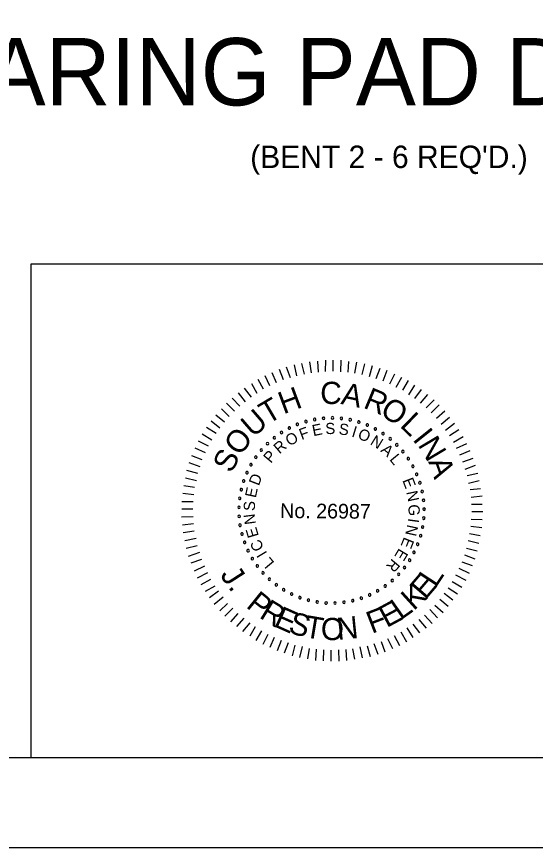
# Model space of a CAD drawing. Extents: x -125.5 to -89.4, y -5.1 to 16.9.
# Drawn here: x -102.979 to -100.09, y -5.066 to -0.44 of the extents above; entities that cross this region are included whole.
import ezdxf

# ---------------------------------------------------------------- set-up
doc = ezdxf.new("R2010")
doc.units = 0
for name, color, linetype in [('BR_BORDER LINES', 7, 'Continuous'), ('BR_TEXT', 7, 'Continuous'), ('Level 31', 7, 'Continuous')]:
    doc.layers.add(name, color=color, linetype=linetype)

msp = doc.modelspace()

# ---------------------------------------------------------------- linework, layer by layer
at = {"layer": 'BR_BORDER LINES'}
for p, q in [((-102.8989, -1.8161), (-97.5337, -1.8161)), ((-102.8989, -4.5661), (-102.8989, -1.8161)), ((-123.6994, -4.5662), (-90.0334, -4.5662))]:
    msp.add_line(p, q, dxfattribs=at)
at = {"layer": 'BR_TEXT'}
for p, q in [((-101.2977, -2.419), (-101.3015, -2.3581)), ((-101.2582, -2.4168), (-101.2576, -2.3524)), ((-101.2161, -2.4146), (-101.2156, -2.3528)), ((-101.1741, -2.4175), (-101.1718, -2.3531)), ((-101.4937, -2.4629), (-101.5147, -2.4044)), ((-101.4541, -2.4504), (-101.476, -2.3927)), ((-101.418, -2.4404), (-101.4312, -2.3793)), ((-101.3767, -2.4304), (-101.3908, -2.3711)), ((-101.3372, -2.423), (-101.3461, -2.362)), ((-101.1338, -2.4204), (-101.129, -2.3595)), ((-101.0952, -2.425), (-101.0844, -2.3642)), ((-101.0549, -2.4331), (-101.0407, -2.374)), ((-101.0138, -2.4437), (-100.9979, -2.3829)), ((-100.977, -2.4543), (-100.9551, -2.397)), ((-101.5695, -2.4966), (-101.5957, -2.4406)), ((-101.5325, -2.4798), (-101.556, -2.4238)), ((-100.9376, -2.4675), (-100.9157, -2.4093)), ((-100.9017, -2.485), (-100.8738, -2.4294)), ((-100.8658, -2.5024), (-100.8345, -2.4469)), ((-101.6394, -2.5381), (-101.6698, -2.4838)), ((-101.604, -2.5144), (-101.6344, -2.46)), ((-100.8282, -2.5208), (-100.796, -2.467)), ((-100.795, -2.5451), (-100.761, -2.4913)), ((-101.7041, -2.5847), (-101.744, -2.5346)), ((-101.6704, -2.5593), (-101.7095, -2.5083)), ((-100.7617, -2.5668), (-100.7252, -2.5165)), ((-100.7293, -2.5928), (-100.6886, -2.5434)), ((-101.7369, -2.6094), (-101.7786, -2.5644)), ((-100.6977, -2.618), (-100.6545, -2.5737)), ((-101.7958, -2.6673), (-101.8392, -2.6248)), ((-101.7663, -2.6366), (-101.8106, -2.5925)), ((-100.6697, -2.6456), (-100.6264, -2.6022)), ((-100.6416, -2.6768), (-100.594, -2.6351)), ((-101.8209, -2.6988), (-101.8704, -2.6598)), ((-100.6144, -2.7088), (-100.5677, -2.6705)), ((-101.8686, -2.761), (-101.9224, -2.728)), ((-101.8469, -2.732), (-101.8964, -2.6922)), ((-100.5906, -2.7424), (-100.5414, -2.7033)), ((-101.893, -2.7977), (-101.9467, -2.7656)), ((-100.5686, -2.7718), (-100.516, -2.7396)), ((-101.9104, -2.8319), (-101.9668, -2.804)), ((-100.5466, -2.8089), (-100.4931, -2.7776)), ((-100.5288, -2.8433), (-100.4711, -2.8164)), ((-101.9279, -2.8687), (-101.9852, -2.8433)), ((-100.5111, -2.8804), (-100.4543, -2.856)), ((-101.9454, -2.9072), (-102.0035, -2.8852)), ((-100.4943, -2.9192), (-100.4374, -2.8982)), ((-101.9577, -2.9474), (-102.0193, -2.9246)), ((-100.4809, -2.9596), (-100.4232, -2.9378)), ((-101.97, -2.9833), (-102.0308, -2.9682)), ((-100.4708, -2.9957), (-100.4107, -2.9816)), ((-101.9878, -3.0613), (-102.0487, -3.0531)), ((-101.9772, -3.0253), (-102.0397, -3.0094)), ((-100.4626, -3.0378), (-100.4024, -3.0229)), ((-101.9925, -3.1024), (-102.0542, -3.0951)), ((-100.4543, -3.074), (-100.3951, -3.0667)), ((-101.9954, -3.1419), (-102.0597, -3.1414)), ((-100.4478, -3.1152), (-100.3868, -3.1088)), ((-101.9974, -3.183), (-102.06, -3.1825)), ((-100.4464, -3.1547), (-100.3863, -3.1552)), ((-101.9961, -3.226), (-102.0604, -3.2272)), ((-100.4442, -3.1959), (-100.3833, -3.1964)), ((-101.9938, -3.2646), (-102.0556, -3.2718)), ((-100.4492, -3.2774), (-100.3883, -3.2856)), ((-100.4471, -3.2388), (-100.3871, -3.241)), ((-101.9898, -3.3058), (-102.0509, -3.3148)), ((-100.4564, -3.3185), (-100.3972, -3.3284)), ((-101.9799, -3.3454), (-102.0426, -3.3586)), ((-100.4653, -3.3579), (-100.4053, -3.3721)), ((-101.9733, -3.3875), (-102.0344, -3.4016)), ((-100.4742, -3.3999), (-100.4143, -3.415)), ((-101.9616, -3.4245), (-102.0236, -3.4454)), ((-101.95, -3.4632), (-102.0085, -3.4842)), ((-100.4848, -3.4367), (-100.4275, -3.4586)), ((-101.9331, -3.5003), (-101.9908, -3.5272)), ((-100.5163, -3.512), (-100.4599, -3.5399)), ((-100.4989, -3.4752), (-100.4424, -3.4971)), ((-101.9162, -3.5364), (-101.9731, -3.566)), ((-100.5346, -3.5479), (-100.4774, -3.5784)), ((-101.8994, -3.5735), (-101.9537, -3.6048)), ((-100.553, -3.5846), (-100.5, -3.6168)), ((-101.8756, -3.6106), (-101.93, -3.6419)), ((-101.8544, -3.6399), (-101.9045, -3.6764)), ((-100.5981, -3.6503), (-100.5495, -3.6876)), ((-100.5756, -3.6213), (-100.5235, -3.6535)), ((-101.829, -3.6736), (-101.8791, -3.7127)), ((-100.6224, -3.6836), (-100.5764, -3.7234)), ((-101.8043, -3.7073), (-101.8485, -3.7481)), ((-101.7754, -3.7333), (-101.8204, -3.7784)), ((-100.6787, -3.7423), (-100.6362, -3.7882)), ((-100.6502, -3.7168), (-100.6033, -3.7584)), ((-101.7465, -3.7636), (-101.7889, -3.8095)), ((-101.714, -3.7895), (-101.7548, -3.8364)), ((-100.7073, -3.7721), (-100.6648, -3.8188)), ((-101.6808, -3.8156), (-101.7207, -3.8633)), ((-101.6501, -3.8373), (-101.6814, -3.8894)), ((-100.772, -3.8231), (-100.7364, -3.8714)), ((-100.7392, -3.7976), (-100.6993, -3.8452)), ((-101.6151, -3.8599), (-101.6464, -3.9137)), ((-101.5809, -3.8799), (-101.608, -3.9355)), ((-100.8773, -3.8857), (-100.8468, -3.9418)), ((-100.8393, -3.8663), (-100.808, -3.9206)), ((-100.8057, -3.8443), (-100.7727, -3.8969)), ((-101.5442, -3.8974), (-101.5687, -3.953)), ((-101.5057, -3.9149), (-101.5276, -3.9713)), ((-101.4663, -3.9272), (-101.4891, -3.9854)), ((-100.9892, -3.9311), (-100.9682, -3.9897)), ((-100.9496, -3.9194), (-100.9286, -3.9763)), ((-100.9135, -3.9026), (-100.8865, -3.9586)), ((-101.4304, -3.9395), (-101.4446, -3.9986)), ((-101.3892, -3.9467), (-101.4044, -4.0084)), ((-101.3499, -3.9582), (-101.3598, -4.0165)), ((-101.3104, -3.9628), (-101.3152, -4.0246)), ((-101.271, -3.9657), (-101.2715, -4.0275)), ((-101.229, -3.9686), (-101.2295, -4.0296)), ((-101.1869, -3.9664), (-101.1857, -4.0282)), ((-101.1466, -3.9642), (-101.1428, -4.026)), ((-101.1079, -3.9602), (-101.098, -4.0186)), ((-101.0675, -3.9494), (-101.0542, -4.0113)), ((-101.0262, -3.9429), (-101.0112, -4.0022))]:
    msp.add_line(p, q, dxfattribs=at)
for centre, start, end in [((-101.3196, -2.6831), 10.6038, 190.6038), ((-101.3196, -2.6831), 190.6038, 10.6038), ((-101.2702, -2.6764), 5.0653, 185.0653), ((-101.2702, -2.6764), 185.0653, 5.0653), ((-101.2204, -2.6745), 359.5268, 179.5268), ((-101.2204, -2.6745), 179.5268, 359.5268), ((-101.1707, -2.6774), 173.9884, 353.9884), ((-101.1707, -2.6774), 353.9884, 173.9884), ((-101.1214, -2.6851), 348.4499, 168.4499), ((-101.4607, -2.7311), 27.2191, 207.2191), ((-101.4607, -2.7311), 207.2191, 27.2191), ((-101.4153, -2.7106), 21.6807, 201.6807), ((-101.4153, -2.7106), 201.6807, 21.6807), ((-101.3681, -2.6945), 16.1422, 196.1422), ((-101.3681, -2.6945), 196.1422, 16.1422), ((-101.1214, -2.6851), 168.4499, 348.4499), ((-101.0732, -2.6976), 162.9114, 342.9114), ((-101.0732, -2.6976), 342.9114, 162.9114), ((-101.0263, -2.7146), 157.373, 337.373), ((-101.0263, -2.7146), 337.373, 157.373), ((-100.9814, -2.736), 331.8345, 151.8345), ((-101.5039, -2.7559), 32.7576, 212.7576), ((-101.5039, -2.7559), 212.7576, 32.7576), ((-100.9814, -2.736), 151.8345, 331.8345), ((-100.9387, -2.7617), 146.2961, 326.2961), ((-100.9387, -2.7617), 326.2961, 146.2961), ((-101.5821, -2.8175), 43.8345, 223.8345), ((-101.5821, -2.8175), 223.8345, 43.8345), ((-101.5445, -2.7848), 38.2961, 218.2961), ((-101.5445, -2.7848), 218.2961, 38.2961), ((-100.8987, -2.7914), 140.7576, 320.7576), ((-100.8987, -2.7914), 320.7576, 140.7576), ((-100.8617, -2.8249), 135.2191, 315.2191), ((-100.8617, -2.8249), 315.2191, 135.2191), ((-101.6164, -2.8536), 49.373, 229.373), ((-101.6164, -2.8536), 229.373, 49.373), ((-100.8282, -2.8617), 129.6807, 309.6807), ((-100.8282, -2.8617), 309.6807, 129.6807), ((-101.6471, -2.8929), 54.9114, 234.9114), ((-101.6471, -2.8929), 234.9114, 54.9114), ((-100.7983, -2.9016), 124.1422, 304.1422), ((-100.7983, -2.9016), 304.1422, 124.1422), ((-101.6738, -2.935), 60.4499, 240.4499), ((-101.6738, -2.935), 240.4499, 60.4499), ((-100.7724, -2.9442), 118.6038, 298.6038), ((-100.7724, -2.9442), 298.6038, 118.6038), ((-101.6964, -2.9794), 65.9884, 245.9884), ((-101.6964, -2.9794), 245.9884, 65.9884), ((-100.7508, -2.9891), 113.0653, 293.0653), ((-100.7508, -2.9891), 293.0653, 113.0653), ((-101.7145, -3.0258), 71.5268, 251.5268), ((-101.7145, -3.0258), 251.5268, 71.5268), ((-100.7336, -3.0359), 107.5268, 287.5268), ((-100.7336, -3.0359), 287.5268, 107.5268), ((-101.7281, -3.0738), 77.0653, 257.0653), ((-101.7281, -3.0738), 257.0653, 77.0653), ((-100.721, -3.0841), 101.9884, 281.9884), ((-100.721, -3.0841), 281.9884, 101.9884), ((-101.737, -3.1228), 82.6038, 262.6038), ((-101.737, -3.1228), 262.6038, 82.6038), ((-100.7131, -3.1333), 96.4499, 276.4499), ((-100.7131, -3.1333), 276.4499, 96.4499), ((-101.7411, -3.1724), 88.1422, 268.1422), ((-101.7411, -3.1724), 268.1422, 88.1422), ((-100.71, -3.183), 90.9114, 270.9114), ((-100.71, -3.183), 270.9114, 90.9114), ((-101.7404, -3.2223), 93.6807, 273.6807), ((-101.7404, -3.2223), 273.6807, 93.6807), ((-100.7118, -3.2328), 85.373, 265.373), ((-100.7118, -3.2328), 265.373, 85.373), ((-101.7349, -3.2718), 99.2191, 279.2191), ((-101.7349, -3.2718), 279.2191, 99.2191), ((-100.7183, -3.2822), 79.8345, 259.8345), ((-100.7183, -3.2822), 259.8345, 79.8345), ((-101.7246, -3.3206), 104.7576, 284.7576), ((-101.7246, -3.3206), 284.7576, 104.7576), ((-100.7295, -3.3308), 74.2961, 254.2961), ((-100.7295, -3.3308), 254.2961, 74.2961), ((-101.7097, -3.3681), 110.2961, 290.2961), ((-101.7097, -3.3681), 290.2961, 110.2961), ((-100.7454, -3.378), 68.7576, 248.7576), ((-100.7454, -3.378), 248.7576, 68.7576), ((-101.6903, -3.414), 115.8345, 295.8345), ((-101.6903, -3.414), 295.8345, 115.8345), ((-100.7658, -3.4235), 63.2191, 243.2191), ((-100.7658, -3.4235), 243.2191, 63.2191), ((-101.6665, -3.4578), 121.373, 301.373), ((-101.6665, -3.4578), 301.373, 121.373), ((-100.7904, -3.4668), 57.6807, 237.6807), ((-100.7904, -3.4668), 237.6807, 57.6807), ((-101.6386, -3.4991), 126.9114, 306.9114), ((-101.6386, -3.4991), 306.9114, 126.9114), ((-100.8192, -3.5075), 52.1422, 232.1422), ((-100.8192, -3.5075), 232.1422, 52.1422), ((-101.6069, -3.5375), 132.4499, 312.4499), ((-101.6069, -3.5375), 312.4499, 132.4499), ((-100.8517, -3.5452), 46.6038, 226.6038), ((-100.8517, -3.5452), 226.6038, 46.6038), ((-101.5716, -3.5727), 137.9884, 317.9884), ((-101.5716, -3.5727), 317.9884, 137.9884), ((-101.5331, -3.6043), 143.5268, 323.5268), ((-101.5331, -3.6043), 323.5268, 143.5268), ((-100.9269, -3.6105), 35.5268, 215.5268), ((-100.9269, -3.6105), 215.5268, 35.5268), ((-100.8877, -3.5797), 41.0653, 221.0653), ((-100.8877, -3.5797), 221.0653, 41.0653), ((-101.4917, -3.632), 149.0653, 329.0653), ((-101.4917, -3.632), 329.0653, 149.0653), ((-101.4478, -3.6556), 154.6038, 334.6038), ((-101.4478, -3.6556), 334.6038, 154.6038), ((-101.0132, -3.6601), 24.4499, 204.4499), ((-100.9688, -3.6374), 29.9884, 209.9884), ((-100.9688, -3.6374), 209.9884, 29.9884), ((-101.4018, -3.6749), 160.1422, 340.1422), ((-101.4018, -3.6749), 340.1422, 160.1422), ((-101.3542, -3.6896), 165.6807, 345.6807), ((-101.3542, -3.6896), 345.6807, 165.6807), ((-101.3054, -3.6997), 351.2191, 171.2191), ((-101.3054, -3.6997), 171.2191, 351.2191), ((-101.2559, -3.705), 356.7576, 176.7576), ((-101.2061, -3.7055), 2.2961, 182.2961), ((-101.1564, -3.7012), 7.8345, 187.8345), ((-101.1564, -3.7012), 187.8345, 7.8345), ((-101.1074, -3.6921), 13.373, 193.373), ((-101.1074, -3.6921), 193.373, 13.373), ((-101.0595, -3.6784), 18.9114, 198.9114), ((-101.0595, -3.6784), 198.9114, 18.9114), ((-101.0132, -3.6601), 204.4499, 24.4499), ((-101.2559, -3.705), 176.7576, 356.7576), ((-101.2061, -3.7055), 182.2961, 2.2961)]:
    msp.add_arc(centre, 0.00701, start, end, dxfattribs=at)
at = {"layer": 'Level 31'}
msp.add_lwpolyline([(-125.5328, -5.0661), (-89.5328, -5.0661), (-89.5328, 16.9339), (-125.5328, 16.9339)], close=True, dxfattribs=at)

# ---------------------------------------------------------------- texts
at = {"layer": 'BR_TEXT'}
for s, height, p in [('BEARING PAD DETAILS - TYPE 2', 0.375, (-103.821, -0.9342)), ("(BENT 2 - 6 REQ'D.)", 0.125, (-101.6784, -1.2831))]:
    msp.add_text(s, height=height, dxfattribs=at).set_placement(p)
for s, height, rotation, p in [('C', 0.1241, 359.5482, (-101.2889, -2.5969)), ('A', 0.1241, 348.1981, (-101.1775, -2.5961)), ('H', 0.1241, 20.3637, (-101.4933, -2.6552)), ('R', 0.1241, 337.4344, (-101.0542, -2.616)), ('T', 0.1241, 30.4992, (-101.5812, -2.7128)), ('O', 0.1239, 326.5869, (-100.962, -2.6528)), ('U', 0.1241, 40.8022, (-101.6624, -2.7875)), ('L', 0.1241, 315.9488, (-100.8494, -2.7205)), ('F', 0.0622, 20.6127, (-101.392, -2.7981)), ('E', 0.0622, 11.4103, (-101.3269, -2.7764)), ('S', 0.0622, 2.208, (-101.2591, -2.7654)), ('S', 0.0622, 352.6608, (-101.1878, -2.7657)), ('I', 0.0622, 343.1136, (-101.1175, -2.7777)), ('I', 0.1241, 308.6613, (-100.778, -2.7948)), ('O', 0.1241, 52.0267, (-101.7369, -2.8914)), ('O', 0.0622, 30.8477, (-101.4594, -2.8341)), ('O', 0.0622, 338.4392, (-101.0841, -2.7878)), ('N', 0.0622, 328.2042, (-101.0145, -2.8192)), ('N', 0.1241, 300.7037, (-100.7474, -2.8242)), ('R', 0.0622, 40.3949, (-101.5156, -2.878)), ('S', 0.1239, 63.2511, (-101.7823, -2.9871)), ('P', 0.0622, 49.9421, (-101.5636, -2.9306)), ('A', 0.0622, 318.657, (-100.9555, -2.8592)), ('L', 0.0622, 309.4546, (-100.9057, -2.9066)), ('A', 0.1241, 289.4792, (-100.6882, -2.9172)), ('D', 0.0622, 69.0364, (-101.6306, -3.0559)), ('E', 0.0622, 291.049, (-100.8319, -3.0219)), ('E', 0.0622, 78.2388, (-101.6472, -3.1226)), ('N', 0.0622, 281.8466, (-100.8097, -3.0869)), ('S', 0.0622, 87.786, (-101.6529, -3.1936)), ('No. 26987', 0.08175, 359.5268, (-101.5118, -3.232)), ('G', 0.0622, 272.2995, (-100.7979, -3.1572)), ('N', 0.0622, 97.3332, (-101.6467, -3.2646)), ('E', 0.0622, 106.5355, (-101.6297, -3.3312)), ('N', 0.0622, 257.7339, (-100.8028, -3.2656)), ('I', 0.0622, 262.4084, (-100.7983, -3.231)), ('C', 0.0622, 116.4266, (-101.5998, -3.3987)), ('E', 0.0622, 248.1867, (-100.8209, -3.3346)), ('I', 0.0622, 121.1011, (-101.5818, -3.4285)), ('E', 0.0622, 238.9844, (-100.8488, -3.3973)), ('L', 0.0622, 129.9595, (-101.5411, -3.4807)), ('R', 0.0622, 229.782, (-100.8865, -3.4548)), ('J', 0.1236, 302.9559, (-101.849, -3.5492)), ('E', 0.1236, 49.3639, (-100.703, -3.6911)), ('L', 0.1236, 56.4247, (-100.6455, -3.6233)), ('K', 0.1236, 42.3031, (-100.7683, -3.7512)), ('.', 0.1236, 309.3974, (-101.8049, -3.6172)), ('P', 0.1236, 321.1035, (-101.7065, -3.7264)), ('R', 0.1236, 328.5359, (-101.6332, -3.7844)), ('E', 0.1236, 28.1814, (-100.9186, -3.8452)), ('L', 0.1236, 35.2422, (-100.8406, -3.8028)), ('E', 0.1236, 335.9684, (-101.5531, -3.8325)), ('F', 0.1236, 21.1206, (-101.0013, -3.8776)), ('S', 0.1236, 343.0292, (-101.4718, -3.8682)), ('T', 0.1236, 350.4617, (-101.3821, -3.8947)), ('O', 0.1236, 358.1419, (-101.2867, -3.9097)), ('N', 0.1236, 5.8221, (-101.1902, -3.9118))]:
    msp.add_text(s, height=height, rotation=rotation, dxfattribs=at).set_placement(p)

doc.saveas('drawing.dxf')
